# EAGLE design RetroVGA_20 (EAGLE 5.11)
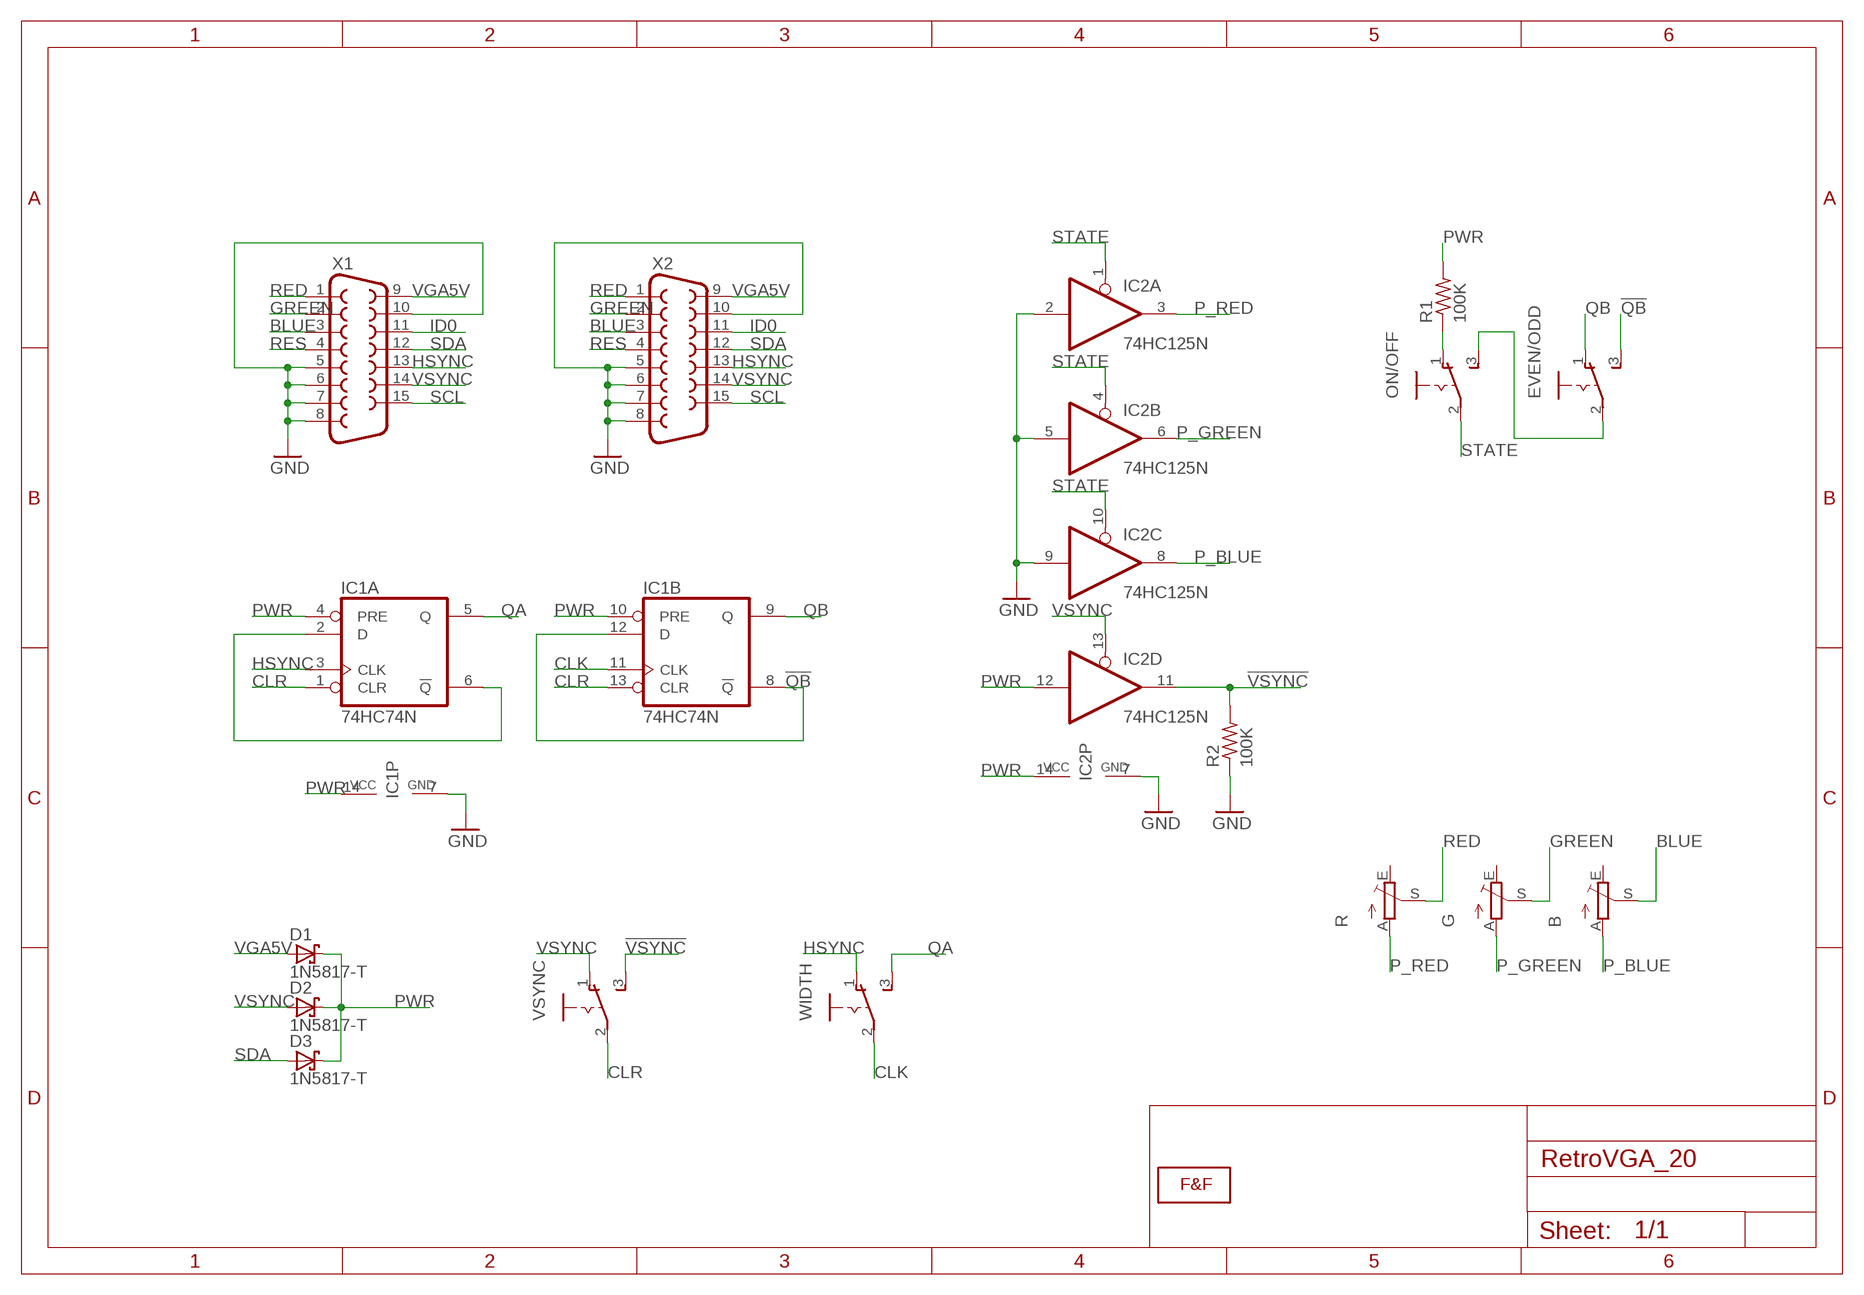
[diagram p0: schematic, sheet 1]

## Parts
B  TRIM_EU-CA6V  [CA6V]
D1  1N5817-T  [DO41-7.6]
D2  1N5817-T  [DO41-7.6]
D3  1N5817-T  [DO41-7.6]
EVEN/ODD  CHAVE  [CHAVE]
G  TRIM_EU-CA6V  [CA6V]
IC1  74HC74N  [DIL14]
IC2  74HC125N  [DIL14]
ON/OFF  CHAVE  [CHAVE]
R  TRIM_EU-CA6V  [CA6V]
R1  100K  R-US_0207/7  [0207/7]
R2  100K  R-US_0207/7  [0207/7]
U$1  LOGOLOGO_WITHOUT_SMOKE_SMALL  [LOGO2_SMALL]
VSYNC  CHAVE  [CHAVE]
WIDTH  CHAVE  [CHAVE]
X1  F15HDH  [HDF15H]
X2  F15HDH  [HDF15H]

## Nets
!QB: EVEN/ODD.3(S) IC1.8(B:!Q) IC1.12(B:D)
!VSYNC: IC2.11(D:O) R2.2 VSYNC.3(S)
BLUE: B.S X1.3 X2.3
CLK: IC1.11(B:CLK) WIDTH.2(P)
CLR: IC1.1(A:CLR) IC1.13(B:CLR) VSYNC.2(P)
GND: IC1.7(P:GND) IC2.2(A:I) IC2.5(B:I) IC2.7(P:GND) IC2.9(C:I) R2.1 X1.5 X1.6 X1.7 X1.8 X1.10 X2.5 X2.6 X2.7 X2.8 X2.10
GREEN: G.S X1.2 X2.2
HSYNC: IC1.3(A:CLK) WIDTH.1(O) X1.13 X2.13
ID0: X1.11 X2.11
N$1: IC1.2(A:D) IC1.6(A:!Q)
N$2: EVEN/ODD.2(P) ON/OFF.3(S)
N$3: ON/OFF.1(O) R1.1
P_BLUE: B.A IC2.8(C:O)
P_GREEN: G.A IC2.6(B:O)
P_RED: IC2.3(A:O) R.A
PWR: D1.C D2.C D3.C IC1.4(A:PRE) IC1.10(B:PRE) IC1.14(P:VCC) IC2.12(D:I) IC2.14(P:VCC) R1.2
QA: IC1.5(A:Q) WIDTH.3(S)
QB: EVEN/ODD.1(O) IC1.9(B:Q)
RED: R.S X1.1 X2.1
RES: X1.4 X2.4
SCL: X1.15 X2.15
SDA: D3.A X1.12 X2.12
STATE: IC2.1(A:OE) IC2.4(B:OE) IC2.10(C:OE) ON/OFF.2(P)
VGA5V: D1.A X1.9 X2.9
VSYNC: D2.A IC2.13(D:OE) VSYNC.1(O) X1.14 X2.14
Unconnected: B.E G.E R.E

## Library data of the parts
B G R = pot:TRIM_EU-: POTENTIOMETER
D1-D3 = diode:1N581*: 1.0A SCHOTTKY BARRIER RECTIFIER
EVEN/ODD ON/OFF VSYNC WIDTH = switch-fef:CHAVE: chave Verificar
IC1 = 74xx-eu:74*74: Dual D type positive edge triggered FLIP FLOP, preset and clear
IC2 = 74xx-eu:74*125: Quad bus BUFFER, 3-state
R1 R2 = rcl:R-US_: RESISTOR, American symbol
U$1 = F&F:LOGO: Faísca e Fumaça Logo
X1 X2 = adafruit:F15: SUB-D HDH is also known as a 'right angle VGA' connector

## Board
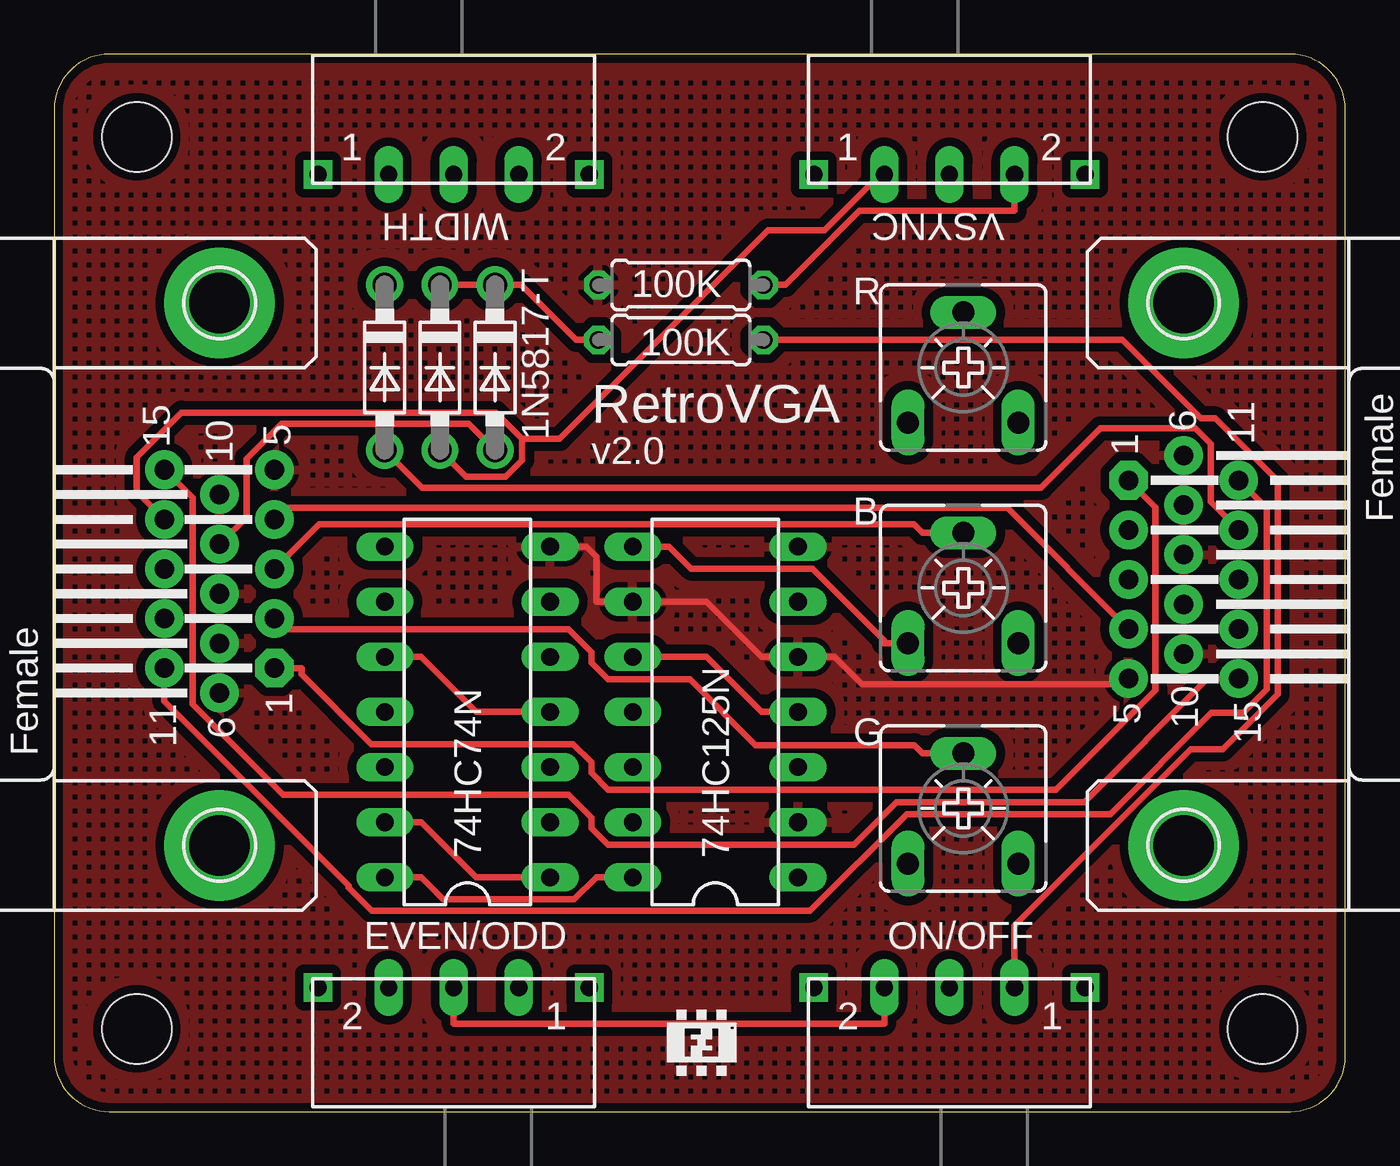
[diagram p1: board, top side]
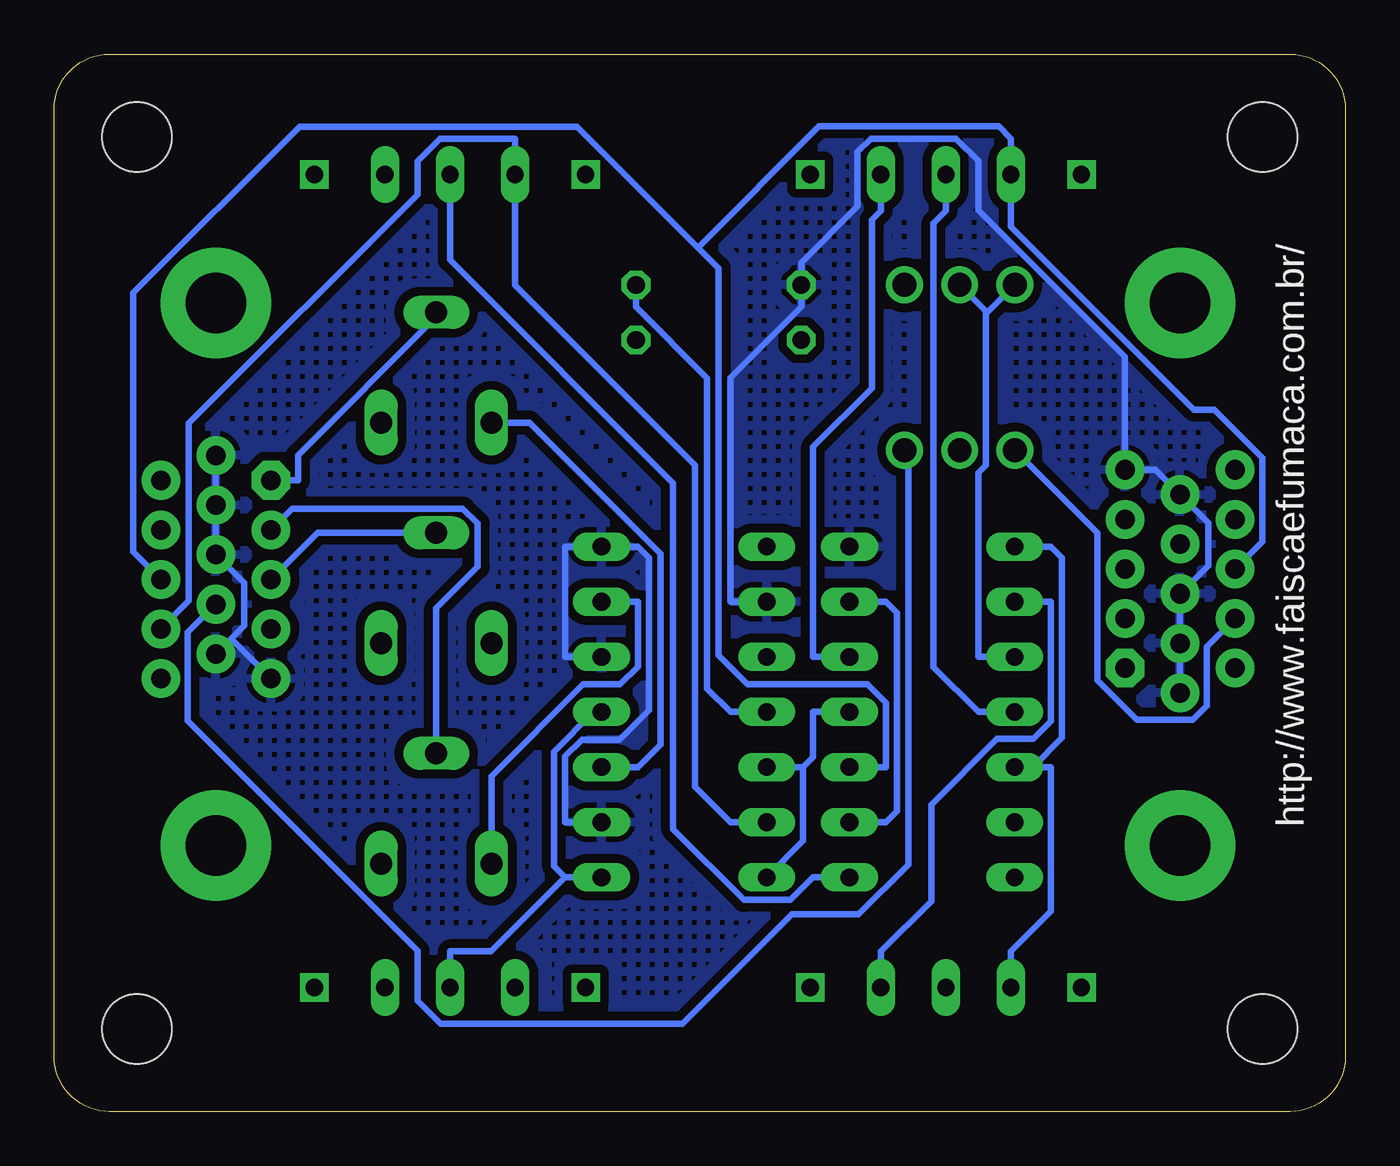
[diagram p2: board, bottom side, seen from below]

Size 59.52 x 48.73 mm. Coordinates in mm from the lower left corner, seen from the top.
Outline: 2.54,48.73 arc90 0,46.19 0,2.54 arc90 2.54,0 56.98,0 arc90 59.52,2.54 59.52,46.19 arc90 56.98,48.73 2.54,48.73
Copper layers (1*16): Top 0.035mm / dielectric 1.5mm / Bottom 0.035mm
Design rules "ITead_rule": minimum track width 6mil, minimum drill 12mil, track to track 6mil, track to pad 6mil, pad to pad 6mil, via to via 6mil, smd to smd 0mil, copper to edge 10mil, drill to drill 10mil, minimum pad ring 10mil, minimum via ring 6mil, stop-mask expansion 2mil, vias tented up to drill 100mil, thermal gap 10mil
Holes 3.2 mm at 3.81,44.92 3.81,3.81 55.72,3.81 55.72,44.92

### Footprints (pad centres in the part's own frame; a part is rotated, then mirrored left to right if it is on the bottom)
CA6V = drill 1.016 long: A -2.54,-2.54; E 2.54,-2.54; S 0,2.54
DO41-7.6 = drill 1.1 pad 1.7 round: A 3.81,0; C -3.81,0
CHAVE = drill 0.8 long: 1 -3,0; 2 0,0; 3 3,0 | drill 0.8 square: P$1 -6.25,0; P$2 6.25,0
DIL14 = drill 0.813 long: 1 -7.62,-3.81; 2 -5.08,-3.81; 3 -2.54,-3.81; 4 0,-3.81; 5 2.54,-3.81; 6 5.08,-3.81; 7 7.62,-3.81; 8 7.62,3.81; 9 5.08,3.81; 10 2.54,3.81; 11 0,3.81; 12 -2.54,3.81; 13 -5.08,3.81; 14 -7.62,3.81
0207/7 = drill 0.813 octagon: 1 -3.81,0; 2 3.81,0
HDF15H = drill 0.9 pad 1.778 octagon: 1 4.329,2.54 | drill 0.9 pad 1.778 round: 2 2.043,2.54; 3 -0.243,2.54; 4 -2.529,2.54; 5 -4.815,2.54; 6 5.472,0; 7 3.186,0; 8 0.9,0; 9 -1.386,0; 10 -3.672,0; 11 4.329,-2.54; 12 2.043,-2.54; 13 -0.243,-2.54; 14 -2.529,-2.54; 15 -4.815,-2.54 | drill 2.8 pad 5.08 round: P$1 -12.5,0; P$2 12.5,0

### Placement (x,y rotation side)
B  41.91,24.13 0 top
D1  20.32,34.29 270 top
D2  17.78,34.29 270 top
D3  15.24,34.29 270 top
EVEN/ODD  18.41,5.71 180 top
G  41.91,13.97 0 top
IC1  19.05,18.41 90 top
IC2  30.48,18.41 90 top
ON/OFF  41.27,5.71 180 top
R  41.91,34.29 0 top
R1  28.89,35.56 180 top
R2  28.89,38.1 0 top
U$1  29.84,3.17 0 top
VSYNC  41.27,43.18 0 top
WIDTH  18.41,43.18 0 top
X1  7.62,24.77 270 top
X2  52.07,24.77 90 top

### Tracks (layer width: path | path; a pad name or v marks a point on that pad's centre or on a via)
!QB
  Bottom 0.305: 14.4,15.88 13.05,17.22 13.05,25.53 13.56,26.04 IC1.8 | 14.4,15.88 13.56,15.88 13.56,9.23 15.41,7.38 EVEN/ODD.3 | 14.4,15.88 IC1.12
!VSYNC
  Top 0.305: R2.2 33.72,38.1 37.13,41.52 44.27,41.52 VSYNC.3
  Bottom 0.305: IC2.11 28.35,18.41 29.42,19.49 29.42,33.81 32.7,37.08 R2.2
BLUE
  Top 0.305: B.S 40.03,26.67 39.63,27.07 12.22,27.07 X1.3
  Bottom 0.305: B.S 47.38,26.67 X2.3
CLK
  Bottom 0.305: IC1.11 16.92,18.41 18.99,20.48 18.99,40.95 18.41,41.52 WIDTH.2
CLR
  Top 0.305: IC1.1 19.46,10.79 16.92,13.34 IC1.13
  Bottom 0.305: VSYNC.2 41.27,39.26 30.99,28.97 30.99,13.02 27.73,9.75 25.58,9.75 24.54,10.79 IC1.1
GND
  Top 0.305: IC1.7 24.54,26.04 24.99,25.58 24.99,23.5 IC2.9 30.07,23.5 32.61,20.95 IC2.5 35.97,20.95 37.23,19.69 49.27,19.69 X2.5
  Bottom 0.305: 51.37,21.79 X2.10 | 51.37,21.79 50.77,22.39 50.77,24.37 X2.8 X2.7 X2.6 | X2.5 51.37,21.79 | IC2.9 28.35,23.5 28.35,33.82 25.08,37.08 R2.1 25.08,39.12 22.48,41.72 22.48,44.23 21.87,44.84 17.94,44.84 16.91,43.81 16.91,41.54 10.16,34.79 X1.5 8.76,29.58 X1.10 6.33,27.14 6.33,25.16 X1.8 X1.7 X1.6 | IC2.2 35.97,13.34 35.97,16.38 35.2,17.14 33.45,17.14 32.09,18.5 32.09,25.52 32.61,26.04 IC2.7 35.97,26.04 35.97,20.95 IC2.5
  pour Bottom (isolate 0.406, hatched): 0,48.26 59.69,48.26 59.69,0 0,0
  pour Top (isolate 0.406, hatched): 0,48.26 59.69,48.26 59.69,0 0,0
GREEN
  Top 0.305: G.S 40.03,16.51 39.65,16.89 32.33,16.89 29.31,19.91 25.54,19.91 24.77,20.69 24.77,21.17 23.71,22.23 10.66,22.23 X1.2
  Bottom 0.305: X2.2 48.55,27.79 40.69,27.79 40,27.11 40,25.1 41.91,23.2 41.91,17.63 | 41.91,17.63 | G.S 41.91,17.63
HSYNC
  Bottom 0.305: 29.84,39.82 28.89,38.88 28.89,21.02 27.55,19.68 22.03,19.68 21.18,18.84 21.18,15.88 IC1.3 | X2.13 55.88,25.79 55.88,37.73 48.21,45.4 35.42,45.4 29.84,39.82 | 29.84,39.82 24.26,45.4 15.97,45.4 15.41,44.84 WIDTH.1 15.41,40.78 6.98,32.35 6.04,32.35 3.83,30.13 3.83,26.26 X1.13
ID0
  Top 0.305: X2.11 55.9,27.81 55.9,19.45 54.81,18.37 53.35,18.37 48.69,13.71 39.31,13.71 34.85,9.26 14.63,9.26 13.56,10.32 13.56,10.42 5.08,18.9 X1.11
N$1
  Bottom 0.305: IC1.2 21.18,13.34 20.68,13.84 20.68,22.99 21.18,23.5 IC1.6
N$2
  Top 0.305: EVEN/ODD.2 18.41,4.05 38.27,4.05 ON/OFF.3
N$3
  Top 0.305: R1.1 49.25,35.56 52.87,31.94 53.54,31.94 56.41,29.08 56.41,19.23 53.87,16.69 52.4,16.69 44.27,8.56 ON/OFF.1
P_BLUE
  Top 0.305: B.A 38.25,21.59 38.25,21.73 34.96,25.02 29.36,25.02 28.35,26.04 IC2.8
P_GREEN
  Bottom 0.305: IC2.6 32.61,23.5 32.61,20.51 33.44,19.68 35.14,19.68 39.37,15.46 G.A
P_RED
  Bottom 0.305: IC2.3 32.61,15.88 31.57,16.91 31.57,25.71 37.61,31.75 R.A
PWR
  Top 0.305: IC1.14 16.92,10.79 17.93,9.78 23.98,9.78 24.99,10.79 IC2.14 | D2.C D1.C 21.53,38.1 24.07,35.56 R1.2 | IC1.10 16.92,20.95 19.46,18.41 IC1.4
  Bottom 0.305: 16.56,36.88 D2.C | 16.56,36.88 16.56,29.8 16.92,29.44 16.92,20.95 IC1.10 | 16.56,36.88 16.46,36.88 D3.C | IC2.14 24.99,12.47 24.99,15.88 | 24.99,15.88 IC2.12 | IC1.4 24.54,18.41 24.54,16.33 24.99,15.88
QA
  Bottom 0.305: IC1.5 24.54,20.95 24.54,30.64 21.83,33.34 21.83,41.1 21.41,41.52 WIDTH.3
QB
  Bottom 0.305: EVEN/ODD.1 21.41,7.38 19.09,9.7 19.09,14.14 16.06,17.18 14.38,17.18 13.56,17.99 13.56,23.5 IC1.9
RED
  Top 0.305: X1.1 11.4,20.44 11.4,20.15 14.61,16.94 23.91,16.94 24.77,16.09 24.77,15.61 25.54,14.83 46.19,14.83 50.77,19.42 50.77,27.85 X2.1
  Bottom 0.305: X2.1 48.28,29.09 48.28,30.26 41.99,36.55 41.91,36.55 R.S
RES
  Top 0.305: X2.4 43.95,27.82 10.69,27.82 X1.4
SCL
  Top 0.305: X2.15 53.17,19.95 47.49,14.26 38.84,14.26 36.86,12.29 25.54,12.29 24.77,13.07 24.77,13.55 23.71,14.61 10.55,14.61 6.38,18.78 6.38,28.29 X1.15
SDA
  Top 0.305: X2.12 53.31,28.1 53.31,30.78 52.61,31.48 48.23,31.48 45.5,28.75 16.97,28.75 D3.A
  Bottom 0.305: D3.A 11.44,26.68 11.44,19.88 9.61,18.05 7.03,18.05 6.38,18.7 6.38,21.43 X1.12
STATE
  Top 0.305: IC2.4 32.61,18.41 30.07,20.95 IC2.10
  Bottom 0.305: ON/OFF.2 41.27,7.38 39.38,7.38 35.97,10.79 | 35.97,10.79 36.48,11.3 36.48,16.59 34.65,18.41 IC2.4 | IC2.1 35.97,10.79
VGA5V
  Top 0.305: D1.A 19.1,31.7 10.48,31.7 8.87,30.09 8.87,27.4 X1.9
  Bottom 0.305: X2.9 53.37,22.08 53.37,18 42.77,7.41 42.77,5.12 41.7,4.04 30.57,4.04 25.52,9.1 22.44,9.1 20.15,11.39 20.15,30.31 D1.A
VSYNC
  Top 0.305: 21.58,31 21.58,30.02 20.82,29.27 18.99,29.27 D2.A | X1.14 3.8,28.57 3.8,30.16 5.86,32.21 20.36,32.21 21.58,31 | VSYNC.1 38.08,43.18 35.51,40.61 32.92,40.61 23.31,31 21.58,31
  Bottom 0.305: X2.14 53.31,23.53 53.31,31.72 42.77,42.26 42.77,43.8 41.73,44.84 38.27,44.84 VSYNC.1 38.27,38.08 29.97,29.78 29.97,14.96 28.35,13.34 IC2.13

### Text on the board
tPlace: RetroVGA | v2.0
bPlace: http://www.faiscaefumaca.com.br/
